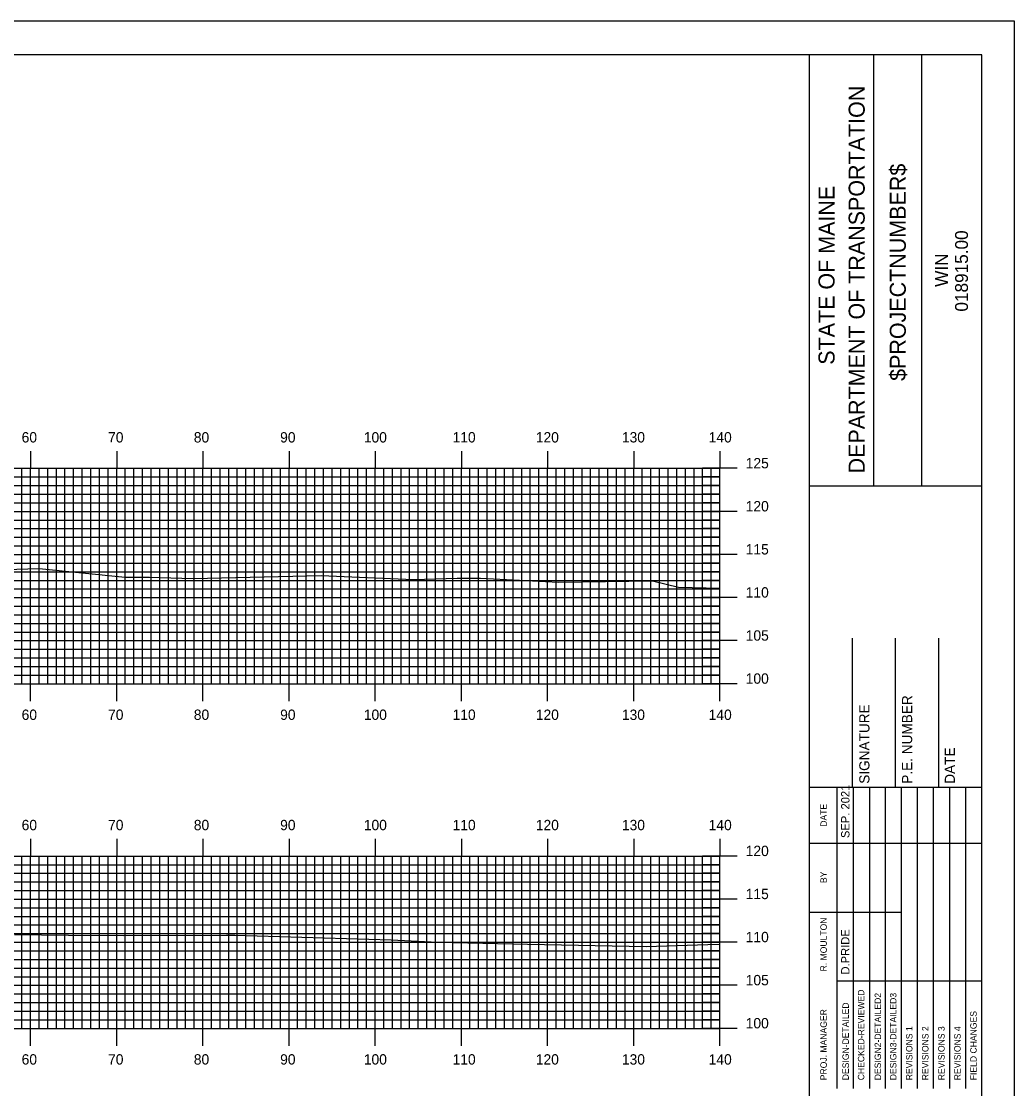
# Model space of a CAD drawing. Extents: x 1766120 to 1766463, y 442591 to 442811.
# Drawn here: x 1766344.3 to 1766459.6, y 442686.7 to 442810.5 of the extents above; entities that cross this region are included whole.
import ezdxf

# ---------------------------------------------------------------- set-up
doc = ezdxf.new("R2010")
doc.units = 0
for name, color, linetype in [('BORDER', 7, 'Continuous'), ('H_V ANNOTATION', 7, 'Continuous'), ('MAJOR', 7, 'Continuous'), ('MINOR', 7, 'Continuous'), ('PLOT BOUNDARY', 7, 'Continuous'), ('S_Roadway_Centerline', 7, 'Continuous')]:
    doc.layers.add(name, color=color, linetype=linetype)

msp = doc.modelspace()

# ---------------------------------------------------------------- linework, layer by layer
at = {"layer": 'BORDER'}
for p, q in [((1766435.8, 442596.67), (1766435.8, 442806.67)), ((1766443.25, 442756.66), (1766443.25, 442806.66)), ((1766448.84, 442756.66), (1766448.84, 442806.66)), ((1766435.8, 442756.65), (1766455.8, 442756.65)), ((1766440.8, 442721.67), (1766440.8, 442738.97)), ((1766445.8, 442721.67), (1766445.8, 442738.97)), ((1766450.8, 442721.67), (1766450.8, 442738.97)), ((1766435.8, 442721.67), (1766455.8, 442721.67))]:
    msp.add_line(p, q, dxfattribs=at)
msp.add_lwpolyline([(1766135.8, 442596.67), (1766455.8, 442596.67), (1766455.8, 442806.67), (1766135.8, 442806.67)], close=True, dxfattribs=at)
for points in [[(1766439.03, 442715.17), (1766439.03, 442721.67)], [(1766440.89, 442686.68), (1766440.89, 442721.67)], [(1766442.76, 442721.67), (1766442.76, 442686.68)], [(1766444.62, 442686.68), (1766444.62, 442721.67)], [(1766446.48, 442686.68), (1766446.48, 442721.67)], [(1766448.35, 442686.68), (1766448.35, 442721.67)], [(1766450.21, 442686.68), (1766450.21, 442721.67)], [(1766452.07, 442686.68), (1766452.07, 442721.67)], [(1766453.94, 442686.68), (1766453.94, 442721.67)], [(1766439.03, 442686.68), (1766439.03, 442720.26)], [(1766435.8, 442715.17), (1766455.8, 442715.17)], [(1766435.8, 442707.17), (1766439.03, 442707.17)], [(1766439.03, 442707.17), (1766446.48, 442707.17)], [(1766439.03, 442699.17), (1766455.8, 442699.17)]]:
    msp.add_lwpolyline(points, dxfattribs=at)
at = {"layer": 'MAJOR'}
for p, q in [((1766345.4, 442760.67), (1766345.4, 442758.67)), ((1766355.4, 442760.67), (1766355.4, 442758.67)), ((1766365.4, 442760.67), (1766365.4, 442758.67)), ((1766375.4, 442760.67), (1766375.4, 442758.67)), ((1766385.4, 442760.67), (1766385.4, 442758.67)), ((1766395.4, 442760.67), (1766395.4, 442758.67)), ((1766405.4, 442760.67), (1766405.4, 442758.67)), ((1766415.4, 442760.67), (1766415.4, 442758.67)), ((1766425.4, 442760.67), (1766425.4, 442758.67)), ((1766145.4, 442758.67), (1766425.4, 442758.67)), ((1766145.4, 442758.67), (1766425.4, 442758.67)), ((1766345.4, 442733.67), (1766345.4, 442758.67)), ((1766355.4, 442733.67), (1766355.4, 442758.67)), ((1766365.4, 442733.67), (1766365.4, 442758.67)), ((1766375.4, 442733.67), (1766375.4, 442758.67)), ((1766385.4, 442733.67), (1766385.4, 442758.67)), ((1766395.4, 442733.67), (1766395.4, 442758.67)), ((1766405.4, 442733.67), (1766405.4, 442758.67)), ((1766415.4, 442733.67), (1766415.4, 442758.67)), ((1766427.4, 442758.67), (1766423.39, 442758.67)), ((1766425.4, 442733.67), (1766425.4, 442758.67)), ((1766425.4, 442733.67), (1766425.4, 442758.67)), ((1766145.4, 442753.67), (1766425.4, 442753.67)), ((1766427.4, 442753.67), (1766423.39, 442753.67)), ((1766145.4, 442748.67), (1766425.4, 442748.67)), ((1766427.4, 442748.67), (1766423.39, 442748.67)), ((1766145.4, 442743.67), (1766425.4, 442743.67)), ((1766427.4, 442743.67), (1766423.39, 442743.67)), ((1766145.4, 442738.67), (1766425.4, 442738.67)), ((1766427.4, 442738.67), (1766423.39, 442738.67)), ((1766145.4, 442733.67), (1766425.4, 442733.67)), ((1766145.4, 442733.67), (1766425.4, 442733.67)), ((1766345.4, 442731.66), (1766345.4, 442733.67)), ((1766355.4, 442731.66), (1766355.4, 442733.67)), ((1766365.4, 442731.66), (1766365.4, 442733.67)), ((1766375.4, 442731.66), (1766375.4, 442733.67)), ((1766385.4, 442731.66), (1766385.4, 442733.67)), ((1766395.4, 442731.66), (1766395.4, 442733.67)), ((1766405.4, 442731.66), (1766405.4, 442733.67)), ((1766415.4, 442731.66), (1766415.4, 442733.67)), ((1766427.4, 442733.67), (1766423.39, 442733.67)), ((1766425.4, 442731.66), (1766425.4, 442733.67)), ((1766345.4, 442715.67), (1766345.4, 442713.67)), ((1766355.4, 442715.67), (1766355.4, 442713.67)), ((1766365.4, 442715.67), (1766365.4, 442713.67)), ((1766375.4, 442715.67), (1766375.4, 442713.67)), ((1766385.4, 442715.67), (1766385.4, 442713.67)), ((1766395.4, 442715.67), (1766395.4, 442713.67)), ((1766405.4, 442715.67), (1766405.4, 442713.67)), ((1766415.4, 442715.67), (1766415.4, 442713.67)), ((1766425.4, 442715.67), (1766425.4, 442713.67)), ((1766145.4, 442713.67), (1766425.4, 442713.67)), ((1766145.4, 442713.67), (1766425.4, 442713.67)), ((1766345.4, 442693.67), (1766345.4, 442713.67)), ((1766355.4, 442693.67), (1766355.4, 442713.67)), ((1766365.4, 442693.67), (1766365.4, 442713.67)), ((1766375.4, 442693.67), (1766375.4, 442713.67)), ((1766385.4, 442693.67), (1766385.4, 442713.67)), ((1766395.4, 442693.67), (1766395.4, 442713.67)), ((1766405.4, 442693.67), (1766405.4, 442713.67)), ((1766415.4, 442693.67), (1766415.4, 442713.67)), ((1766427.4, 442713.67), (1766423.39, 442713.67)), ((1766425.4, 442693.67), (1766425.4, 442713.67)), ((1766425.4, 442693.67), (1766425.4, 442713.67)), ((1766145.4, 442708.67), (1766425.4, 442708.67)), ((1766427.4, 442708.67), (1766423.39, 442708.67)), ((1766145.4, 442703.67), (1766425.4, 442703.67)), ((1766427.4, 442703.67), (1766423.39, 442703.67)), ((1766145.4, 442698.67), (1766425.4, 442698.67)), ((1766427.4, 442698.67), (1766423.39, 442698.67)), ((1766145.4, 442693.67), (1766425.4, 442693.67)), ((1766145.4, 442693.67), (1766425.4, 442693.67)), ((1766345.4, 442691.66), (1766345.4, 442693.67)), ((1766355.4, 442691.66), (1766355.4, 442693.67)), ((1766365.4, 442691.66), (1766365.4, 442693.67)), ((1766375.4, 442691.66), (1766375.4, 442693.67)), ((1766385.4, 442691.66), (1766385.4, 442693.67)), ((1766395.4, 442691.66), (1766395.4, 442693.67)), ((1766405.4, 442691.66), (1766405.4, 442693.67)), ((1766415.4, 442691.66), (1766415.4, 442693.67)), ((1766427.4, 442693.67), (1766423.39, 442693.67)), ((1766425.4, 442691.66), (1766425.4, 442693.67))]:
    msp.add_line(p, q, dxfattribs=at)
at = {"layer": 'MINOR'}
for p, q in [((1766344.4, 442733.67), (1766344.4, 442758.67)), ((1766346.4, 442733.67), (1766346.4, 442758.67)), ((1766347.4, 442733.67), (1766347.4, 442758.67)), ((1766348.4, 442733.67), (1766348.4, 442758.67)), ((1766349.4, 442733.67), (1766349.4, 442758.67)), ((1766350.4, 442733.67), (1766350.4, 442758.67)), ((1766351.4, 442733.67), (1766351.4, 442758.67)), ((1766352.4, 442733.67), (1766352.4, 442758.67)), ((1766353.4, 442733.67), (1766353.4, 442758.67)), ((1766354.4, 442733.67), (1766354.4, 442758.67)), ((1766356.4, 442733.67), (1766356.4, 442758.67)), ((1766357.4, 442733.67), (1766357.4, 442758.67)), ((1766358.4, 442733.67), (1766358.4, 442758.67)), ((1766359.4, 442733.67), (1766359.4, 442758.67)), ((1766360.4, 442733.67), (1766360.4, 442758.67)), ((1766361.4, 442733.67), (1766361.4, 442758.67)), ((1766362.4, 442733.67), (1766362.4, 442758.67)), ((1766363.4, 442733.67), (1766363.4, 442758.67)), ((1766364.4, 442733.67), (1766364.4, 442758.67)), ((1766366.4, 442733.67), (1766366.4, 442758.67)), ((1766367.4, 442733.67), (1766367.4, 442758.67)), ((1766368.4, 442733.67), (1766368.4, 442758.67)), ((1766369.4, 442733.67), (1766369.4, 442758.67)), ((1766370.4, 442733.67), (1766370.4, 442758.67)), ((1766371.4, 442733.67), (1766371.4, 442758.67)), ((1766372.4, 442733.67), (1766372.4, 442758.67)), ((1766373.4, 442733.67), (1766373.4, 442758.67)), ((1766374.4, 442733.67), (1766374.4, 442758.67)), ((1766376.4, 442733.67), (1766376.4, 442758.67)), ((1766377.4, 442733.67), (1766377.4, 442758.67)), ((1766378.4, 442733.67), (1766378.4, 442758.67)), ((1766379.4, 442733.67), (1766379.4, 442758.67)), ((1766380.4, 442733.67), (1766380.4, 442758.67)), ((1766381.4, 442733.67), (1766381.4, 442758.67)), ((1766382.4, 442733.67), (1766382.4, 442758.67)), ((1766383.4, 442733.67), (1766383.4, 442758.67)), ((1766384.4, 442733.67), (1766384.4, 442758.67)), ((1766386.4, 442733.67), (1766386.4, 442758.67)), ((1766387.4, 442733.67), (1766387.4, 442758.67)), ((1766388.4, 442733.67), (1766388.4, 442758.67)), ((1766389.4, 442733.67), (1766389.4, 442758.67)), ((1766390.4, 442733.67), (1766390.4, 442758.67)), ((1766391.4, 442733.67), (1766391.4, 442758.67)), ((1766392.4, 442733.67), (1766392.4, 442758.67)), ((1766393.4, 442733.67), (1766393.4, 442758.67)), ((1766394.4, 442733.67), (1766394.4, 442758.67)), ((1766396.4, 442733.67), (1766396.4, 442758.67)), ((1766397.4, 442733.67), (1766397.4, 442758.67)), ((1766398.4, 442733.67), (1766398.4, 442758.67)), ((1766399.4, 442733.67), (1766399.4, 442758.67)), ((1766400.4, 442733.67), (1766400.4, 442758.67)), ((1766401.4, 442733.67), (1766401.4, 442758.67)), ((1766402.4, 442733.67), (1766402.4, 442758.67)), ((1766403.4, 442733.67), (1766403.4, 442758.67)), ((1766404.4, 442733.67), (1766404.4, 442758.67)), ((1766406.4, 442733.67), (1766406.4, 442758.67)), ((1766407.4, 442733.67), (1766407.4, 442758.67)), ((1766408.4, 442733.67), (1766408.4, 442758.67)), ((1766409.4, 442733.67), (1766409.4, 442758.67)), ((1766410.4, 442733.67), (1766410.4, 442758.67)), ((1766411.4, 442733.67), (1766411.4, 442758.67)), ((1766412.4, 442733.67), (1766412.4, 442758.67)), ((1766413.4, 442733.67), (1766413.4, 442758.67)), ((1766414.4, 442733.67), (1766414.4, 442758.67)), ((1766416.4, 442733.67), (1766416.4, 442758.67)), ((1766417.4, 442733.67), (1766417.4, 442758.67)), ((1766418.4, 442733.67), (1766418.4, 442758.67)), ((1766419.4, 442733.67), (1766419.4, 442758.67)), ((1766420.4, 442733.67), (1766420.4, 442758.67)), ((1766421.4, 442733.67), (1766421.4, 442758.67)), ((1766422.4, 442733.67), (1766422.4, 442758.67)), ((1766423.4, 442733.67), (1766423.4, 442758.67)), ((1766424.4, 442733.67), (1766424.4, 442758.67)), ((1766145.4, 442757.67), (1766425.4, 442757.67)), ((1766425.4, 442757.67), (1766423.39, 442757.67)), ((1766145.4, 442756.67), (1766425.4, 442756.67)), ((1766425.4, 442756.67), (1766423.39, 442756.67)), ((1766145.4, 442755.67), (1766425.4, 442755.67)), ((1766425.4, 442755.67), (1766423.39, 442755.67)), ((1766145.4, 442754.67), (1766425.4, 442754.67)), ((1766425.4, 442754.67), (1766423.39, 442754.67)), ((1766145.4, 442752.67), (1766425.4, 442752.67)), ((1766425.4, 442752.67), (1766423.39, 442752.67)), ((1766145.4, 442751.67), (1766425.4, 442751.67)), ((1766425.4, 442751.67), (1766423.39, 442751.67)), ((1766145.4, 442750.67), (1766425.4, 442750.67)), ((1766425.4, 442750.67), (1766423.39, 442750.67)), ((1766145.4, 442749.67), (1766425.4, 442749.67)), ((1766425.4, 442749.67), (1766423.39, 442749.67)), ((1766145.4, 442747.67), (1766425.4, 442747.67)), ((1766425.4, 442747.67), (1766423.39, 442747.67)), ((1766145.4, 442746.67), (1766425.4, 442746.67)), ((1766425.4, 442746.67), (1766423.39, 442746.67)), ((1766145.4, 442745.67), (1766425.4, 442745.67)), ((1766425.4, 442745.67), (1766423.39, 442745.67)), ((1766145.4, 442744.67), (1766425.4, 442744.67)), ((1766425.4, 442744.67), (1766423.39, 442744.67)), ((1766145.4, 442742.67), (1766425.4, 442742.67)), ((1766425.4, 442742.67), (1766423.39, 442742.67)), ((1766145.4, 442741.67), (1766425.4, 442741.67)), ((1766425.4, 442741.67), (1766423.39, 442741.67)), ((1766145.4, 442740.67), (1766425.4, 442740.67)), ((1766425.4, 442740.67), (1766423.39, 442740.67)), ((1766145.4, 442739.67), (1766425.4, 442739.67)), ((1766425.4, 442739.67), (1766423.39, 442739.67)), ((1766145.4, 442737.67), (1766425.4, 442737.67)), ((1766425.4, 442737.67), (1766423.39, 442737.67)), ((1766145.4, 442736.67), (1766425.4, 442736.67)), ((1766425.4, 442736.67), (1766423.39, 442736.67)), ((1766145.4, 442735.67), (1766425.4, 442735.67)), ((1766425.4, 442735.67), (1766423.39, 442735.67)), ((1766145.4, 442734.67), (1766425.4, 442734.67)), ((1766425.4, 442734.67), (1766423.39, 442734.67)), ((1766344.4, 442693.67), (1766344.4, 442713.67)), ((1766346.4, 442693.67), (1766346.4, 442713.67)), ((1766347.4, 442693.67), (1766347.4, 442713.67)), ((1766348.4, 442693.67), (1766348.4, 442713.67)), ((1766349.4, 442693.67), (1766349.4, 442713.67)), ((1766350.4, 442693.67), (1766350.4, 442713.67)), ((1766351.4, 442693.67), (1766351.4, 442713.67)), ((1766352.4, 442693.67), (1766352.4, 442713.67)), ((1766353.4, 442693.67), (1766353.4, 442713.67)), ((1766354.4, 442693.67), (1766354.4, 442713.67)), ((1766356.4, 442693.67), (1766356.4, 442713.67)), ((1766357.4, 442693.67), (1766357.4, 442713.67)), ((1766358.4, 442693.67), (1766358.4, 442713.67)), ((1766359.4, 442693.67), (1766359.4, 442713.67)), ((1766360.4, 442693.67), (1766360.4, 442713.67)), ((1766361.4, 442693.67), (1766361.4, 442713.67)), ((1766362.4, 442693.67), (1766362.4, 442713.67)), ((1766363.4, 442693.67), (1766363.4, 442713.67)), ((1766364.4, 442693.67), (1766364.4, 442713.67)), ((1766366.4, 442693.67), (1766366.4, 442713.67)), ((1766367.4, 442693.67), (1766367.4, 442713.67)), ((1766368.4, 442693.67), (1766368.4, 442713.67)), ((1766369.4, 442693.67), (1766369.4, 442713.67)), ((1766370.4, 442693.67), (1766370.4, 442713.67)), ((1766371.4, 442693.67), (1766371.4, 442713.67)), ((1766372.4, 442693.67), (1766372.4, 442713.67)), ((1766373.4, 442693.67), (1766373.4, 442713.67)), ((1766374.4, 442693.67), (1766374.4, 442713.67)), ((1766376.4, 442693.67), (1766376.4, 442713.67)), ((1766377.4, 442693.67), (1766377.4, 442713.67)), ((1766378.4, 442693.67), (1766378.4, 442713.67)), ((1766379.4, 442693.67), (1766379.4, 442713.67)), ((1766380.4, 442693.67), (1766380.4, 442713.67)), ((1766381.4, 442693.67), (1766381.4, 442713.67)), ((1766382.4, 442693.67), (1766382.4, 442713.67)), ((1766383.4, 442693.67), (1766383.4, 442713.67)), ((1766384.4, 442693.67), (1766384.4, 442713.67)), ((1766386.4, 442693.67), (1766386.4, 442713.67)), ((1766387.4, 442693.67), (1766387.4, 442713.67)), ((1766388.4, 442693.67), (1766388.4, 442713.67)), ((1766389.4, 442693.67), (1766389.4, 442713.67)), ((1766390.4, 442693.67), (1766390.4, 442713.67)), ((1766391.4, 442693.67), (1766391.4, 442713.67)), ((1766392.4, 442693.67), (1766392.4, 442713.67)), ((1766393.4, 442693.67), (1766393.4, 442713.67)), ((1766394.4, 442693.67), (1766394.4, 442713.67)), ((1766396.4, 442693.67), (1766396.4, 442713.67)), ((1766397.4, 442693.67), (1766397.4, 442713.67)), ((1766398.4, 442693.67), (1766398.4, 442713.67)), ((1766399.4, 442693.67), (1766399.4, 442713.67)), ((1766400.4, 442693.67), (1766400.4, 442713.67)), ((1766401.4, 442693.67), (1766401.4, 442713.67)), ((1766402.4, 442693.67), (1766402.4, 442713.67)), ((1766403.4, 442693.67), (1766403.4, 442713.67)), ((1766404.4, 442693.67), (1766404.4, 442713.67)), ((1766406.4, 442693.67), (1766406.4, 442713.67)), ((1766407.4, 442693.67), (1766407.4, 442713.67)), ((1766408.4, 442693.67), (1766408.4, 442713.67)), ((1766409.4, 442693.67), (1766409.4, 442713.67)), ((1766410.4, 442693.67), (1766410.4, 442713.67)), ((1766411.4, 442693.67), (1766411.4, 442713.67)), ((1766412.4, 442693.67), (1766412.4, 442713.67)), ((1766413.4, 442693.67), (1766413.4, 442713.67)), ((1766414.4, 442693.67), (1766414.4, 442713.67)), ((1766416.4, 442693.67), (1766416.4, 442713.67)), ((1766417.4, 442693.67), (1766417.4, 442713.67)), ((1766418.4, 442693.67), (1766418.4, 442713.67)), ((1766419.4, 442693.67), (1766419.4, 442713.67)), ((1766420.4, 442693.67), (1766420.4, 442713.67)), ((1766421.4, 442693.67), (1766421.4, 442713.67)), ((1766422.4, 442693.67), (1766422.4, 442713.67)), ((1766423.4, 442693.67), (1766423.4, 442713.67)), ((1766424.4, 442693.67), (1766424.4, 442713.67)), ((1766145.4, 442712.67), (1766425.4, 442712.67)), ((1766145.4, 442711.67), (1766425.4, 442711.67)), ((1766425.4, 442712.67), (1766423.39, 442712.67)), ((1766425.4, 442711.67), (1766423.39, 442711.67)), ((1766145.4, 442710.67), (1766425.4, 442710.67)), ((1766425.4, 442710.67), (1766423.39, 442710.67)), ((1766145.4, 442709.67), (1766425.4, 442709.67)), ((1766425.4, 442709.67), (1766423.39, 442709.67)), ((1766145.4, 442707.67), (1766425.4, 442707.67)), ((1766145.4, 442706.67), (1766425.4, 442706.67)), ((1766425.4, 442707.67), (1766423.39, 442707.67)), ((1766425.4, 442706.67), (1766423.39, 442706.67)), ((1766145.4, 442705.67), (1766425.4, 442705.67)), ((1766425.4, 442705.67), (1766423.39, 442705.67)), ((1766145.4, 442704.67), (1766425.4, 442704.67)), ((1766425.4, 442704.67), (1766423.39, 442704.67)), ((1766145.4, 442702.67), (1766425.4, 442702.67)), ((1766145.4, 442701.67), (1766425.4, 442701.67)), ((1766425.4, 442702.67), (1766423.39, 442702.67)), ((1766425.4, 442701.67), (1766423.39, 442701.67)), ((1766145.4, 442700.67), (1766425.4, 442700.67)), ((1766425.4, 442700.67), (1766423.39, 442700.67)), ((1766145.4, 442699.67), (1766425.4, 442699.67)), ((1766425.4, 442699.67), (1766423.39, 442699.67)), ((1766145.4, 442697.67), (1766425.4, 442697.67)), ((1766145.4, 442696.67), (1766425.4, 442696.67)), ((1766425.4, 442697.67), (1766423.39, 442697.67)), ((1766425.4, 442696.67), (1766423.39, 442696.67)), ((1766145.4, 442695.67), (1766425.4, 442695.67)), ((1766425.4, 442695.67), (1766423.39, 442695.67)), ((1766145.4, 442694.67), (1766425.4, 442694.67)), ((1766425.4, 442694.67), (1766423.39, 442694.67))]:
    msp.add_line(p, q, dxfattribs=at)
at = {"layer": 'PLOT BOUNDARY'}
msp.add_lwpolyline([(1766119.61, 442590.55), (1766459.61, 442590.55), (1766459.61, 442810.55), (1766119.61, 442810.55)], close=True, dxfattribs=at)
at = {"layer": 'S_Roadway_Centerline'}
for points in [[(1766342.49, 442746.91), (1766346.42, 442747.04), (1766356.4, 442746.04), (1766359.22, 442746.02), (1766360.37, 442745.98), (1766364.28, 442745.89), (1766379.14, 442746.23), (1766389.83, 442745.77), (1766394.92, 442745.93), (1766397.61, 442745.92), (1766406.66, 442745.46), (1766417.57, 442745.62), (1766420.61, 442744.86), (1766425.4, 442744.77)], [(1766343.53, 442704.58), (1766349.79, 442704.47), (1766356.23, 442704.45), (1766368.13, 442704.49), (1766369.1, 442704.49), (1766387.25, 442703.95), (1766392.66, 442703.67), (1766403.09, 442703.46), (1766416.85, 442703.18), (1766423.99, 442703.41), (1766425.4, 442703.44)]]:
    msp.add_lwpolyline(points, dxfattribs=at)

# ---------------------------------------------------------------- texts
at = {"layer": 'BORDER'}
for s, height, p in [('DEPARTMENT OF TRANSPORTATION', 1.8635, (1766442.21, 442758.08)), ('$PROJECTNUMBER$', 1.8635, (1766446.98, 442768.82)), ('STATE OF MAINE', 1.8635, (1766438.71, 442770.69)), ('018915.00', 1.491, (1766454.19, 442776.86)), ('WIN', 1.491, (1766451.87, 442779.73)), ('P.E. NUMBER', 1.1811, (1766447.72, 442722.06)), ('SIGNATURE', 1.181, (1766442.76, 442722.06)), ('DATE', 1.181, (1766452.68, 442722.06)), ('SEP. 2021', 0.969, (1766440.44, 442715.76)), ('DATE', 0.743, (1766437.81, 442717.08)), ('BY', 0.743, (1766437.81, 442710.54)), ('R. MOULTON', 0.745, (1766437.81, 442700.28)), ('D.PRIDE', 0.969, (1766440.44, 442699.92)), ('CHECKED-REVIEWED', 0.7455, (1766442.16, 442687.65)), ('DESIGN2-DETAILED2', 0.7455, (1766444.1, 442687.65)), ('DESIGN3-DETAILED3', 0.7455, (1766445.89, 442687.65)), ('PROJ. MANAGER', 0.7455, (1766437.81, 442687.65)), ('DESIGN-DETAILED', 0.7455, (1766440.37, 442687.65)), ('FIELD CHANGES', 0.7455, (1766455.2, 442687.65)), ('REVISIONS 1', 0.7455, (1766447.75, 442687.65)), ('REVISIONS 2', 0.7455, (1766449.61, 442687.65)), ('REVISIONS 3', 0.7455, (1766451.48, 442687.65)), ('REVISIONS 4', 0.7455, (1766453.34, 442687.65))]:
    msp.add_text(s, height=height, rotation=90, dxfattribs=at).set_placement(p)
at = {"layer": 'H_V ANNOTATION'}
for s, p in [('60', (1766344.37, 442761.67)), ('70', (1766354.4, 442761.67)), ('80', (1766364.35, 442761.67)), ('90', (1766374.37, 442761.67)), ('100', (1766384.08, 442761.67)), ('110', (1766394.38, 442761.67)), ('120', (1766404.04, 442761.67)), ('130', (1766414.03, 442761.67)), ('140', (1766424.1, 442761.67)), ('125', (1766428.4, 442758.67)), ('120', (1766428.4, 442753.67)), ('115', (1766428.4, 442748.67)), ('110', (1766428.4, 442743.67)), ('105', (1766428.4, 442738.67)), ('100', (1766428.4, 442733.67)), ('60', (1766344.37, 442729.47)), ('70', (1766354.4, 442729.47)), ('80', (1766364.35, 442729.47)), ('90', (1766374.37, 442729.47)), ('100', (1766384.08, 442729.47)), ('110', (1766394.38, 442729.47)), ('120', (1766404.04, 442729.47)), ('130', (1766414.03, 442729.47)), ('140', (1766424.1, 442729.47)), ('60', (1766344.37, 442716.67)), ('70', (1766354.4, 442716.67)), ('80', (1766364.35, 442716.67)), ('90', (1766374.37, 442716.67)), ('100', (1766384.08, 442716.67)), ('110', (1766394.38, 442716.67)), ('120', (1766404.04, 442716.67)), ('130', (1766414.03, 442716.67)), ('140', (1766424.1, 442716.67)), ('120', (1766428.4, 442713.67)), ('115', (1766428.4, 442708.67)), ('110', (1766428.4, 442703.67)), ('105', (1766428.4, 442698.67)), ('100', (1766428.4, 442693.67)), ('60', (1766344.37, 442689.47)), ('70', (1766354.4, 442689.47)), ('80', (1766364.35, 442689.47)), ('90', (1766374.37, 442689.47)), ('100', (1766384.08, 442689.47)), ('110', (1766394.38, 442689.47)), ('120', (1766404.04, 442689.47)), ('130', (1766414.03, 442689.47)), ('140', (1766424.1, 442689.47))]:
    msp.add_text(s, height=1.2, dxfattribs=at).set_placement(p)

doc.saveas('drawing.dxf')
